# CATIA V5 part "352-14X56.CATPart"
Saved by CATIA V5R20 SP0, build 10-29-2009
Part number: 352-14X56
Definition: NONE
Nomenclature: 352-14X56
Source: Unknown
Description: 352-14X56
Bounding box of the stored display mesh (mm): x 0 to 56, y -10 to 10, z -10 to 10
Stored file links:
  C:\Users\Utente\Desktop\IO LAVORO\3D X SITO CF\X SITO\PLASTICA\352\352-14X56.CATPart
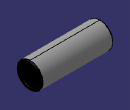
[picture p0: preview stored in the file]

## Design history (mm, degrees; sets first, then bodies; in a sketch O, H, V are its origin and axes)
Body1 "352-14X56" (main body)
  Solid1: solid without history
